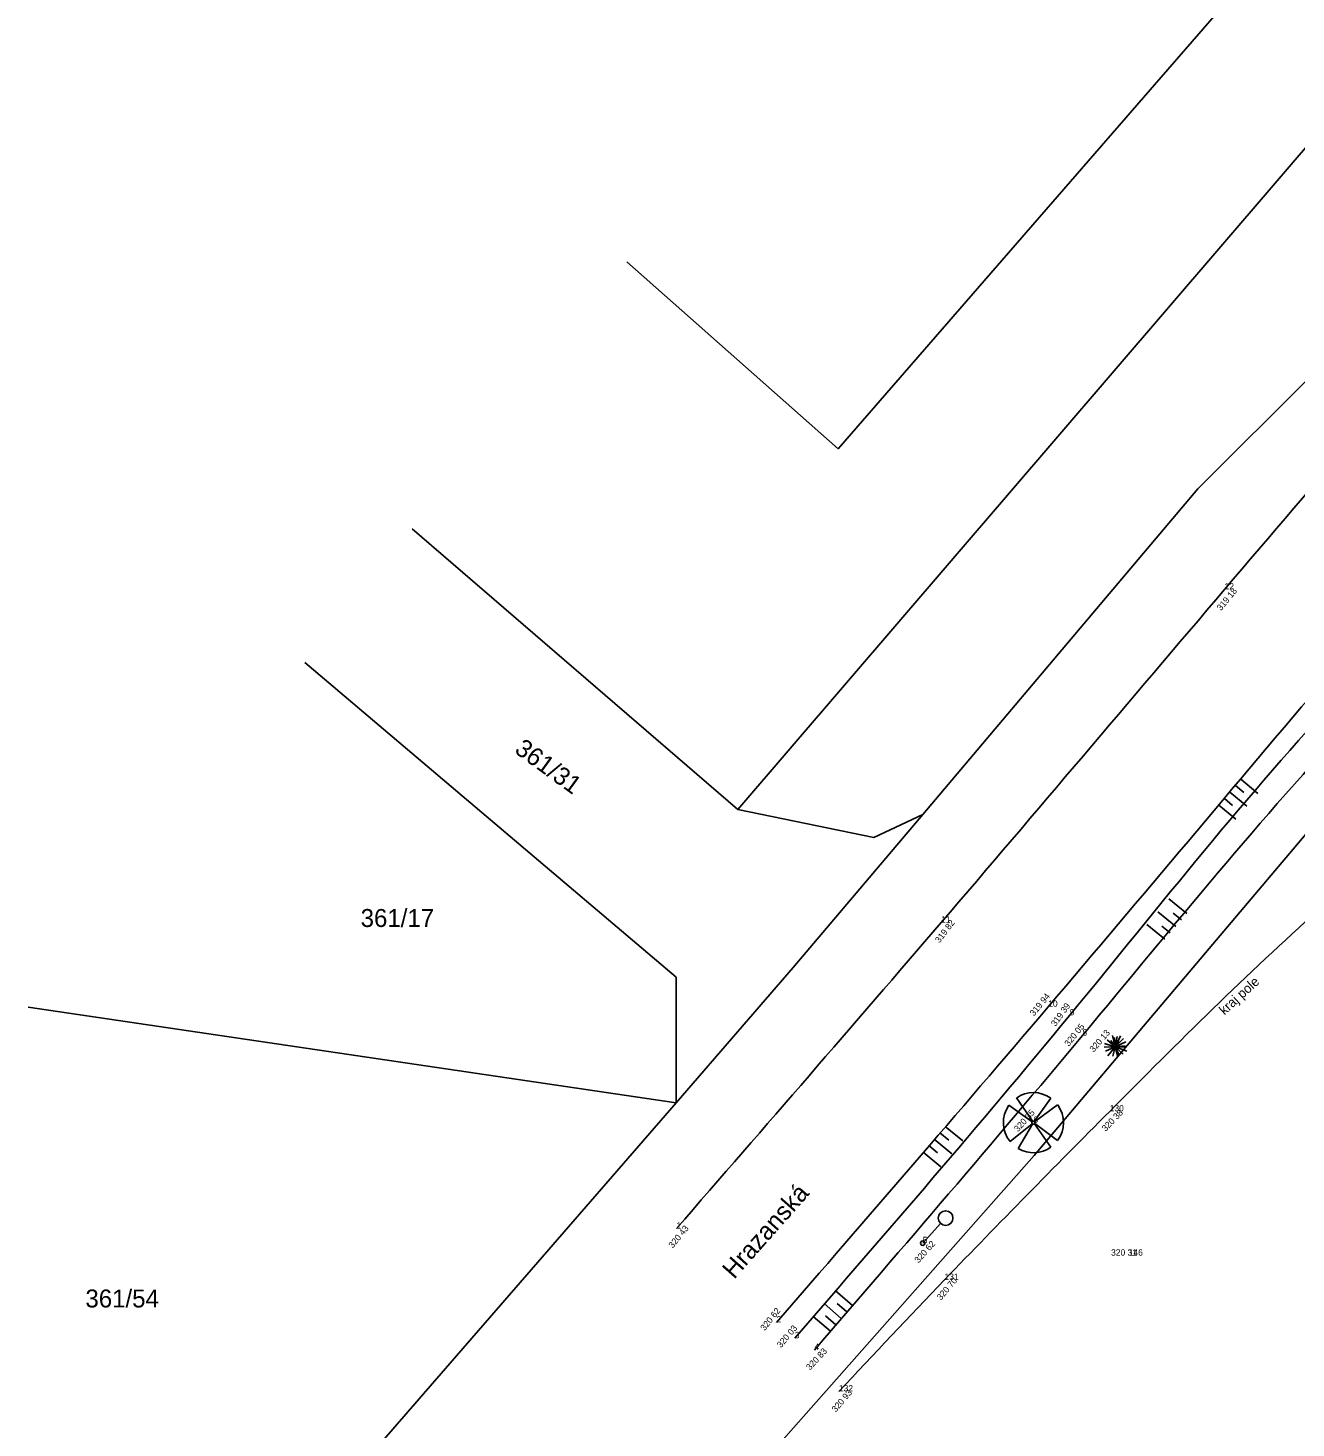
# Model space of a CAD drawing. Extents: x -742884 to -742543, y -1054677 to -1054433.
# Drawn here: x -742813.9 to -742753.9, y -1054546.4 to -1054480.1 of the extents above; entities that cross this region are included whole.
import ezdxf

# ---------------------------------------------------------------- set-up
doc = ezdxf.new("R2010")
doc.units = 0
for name, color, linetype in [('Vrstva 1', 7, 'Continuous'), ('Vrstva 10', 7, 'Continuous'), ('Vrstva 11', 7, 'Continuous'), ('Vrstva 14', 7, 'Continuous'), ('Vrstva 15', 7, 'Continuous'), ('Vrstva 2', 7, 'Continuous'), ('Vrstva 3', 7, 'Continuous'), ('Vrstva 4', 7, 'Continuous'), ('Vrstva 50', 7, 'Continuous')]:
    doc.layers.add(name, color=color, linetype=linetype)

# ---------------------------------------------------------------- blocks, each defined once
blk = doc.blocks.new('Z15')
at = {"layer": 'Vrstva 2'}
for p, q in [((-10, 2), (-8, 6)), ((-10, -2), (-10, 2)), ((-8, 6), (-6, 8)), ((-6, 8), (-2, 10)), ((-2, 10), (2, 10)), ((2, 10), (6, 8)), ((6, 8), (8, 6)), ((8, 6), (10, 2)), ((10, 2), (10, -2)), ((-8, -6), (-10, -2)), ((-6, -8), (-8, -6)), ((-2, -10), (-6, -8)), ((2, -10), (-2, -10)), ((6, -8), (2, -10)), ((8, -6), (6, -8)), ((10, -2), (8, -6))]:
    blk.add_line(p, q, dxfattribs=at)

msp = doc.modelspace()

# ---------------------------------------------------------------- linework, layer by layer
at = {"layer": 'Vrstva 1'}
for p, q in [((-742757.28, -1054506.67), (-742757.28, -1054506.67)), ((-742770.7, -1054522.44), (-742770.7, -1054522.44)), ((-742765.63, -1054526.43), (-742765.63, -1054526.43)), ((-742764.61, -1054526.83), (-742764.61, -1054526.83)), ((-742764.01, -1054527.79), (-742764.01, -1054527.79)), ((-742762.46, -1054528.33), (-742762.46, -1054528.33)), ((-742766.33, -1054531.92), (-742766.33, -1054531.92)), ((-742762.72, -1054531.38), (-742762.72, -1054531.38)), ((-742783.23, -1054536.93), (-742783.23, -1054536.93)), ((-742771.57, -1054537.62), (-742771.57, -1054537.62)), ((-742761.82, -1054538.21), (-742761.82, -1054538.21)), ((-742770.54, -1054539.36), (-742770.54, -1054539.36)), ((-742778.49, -1054541.37), (-742778.49, -1054541.37)), ((-742777.63, -1054542.12), (-742777.63, -1054542.12)), ((-742776.7, -1054542.68), (-742776.7, -1054542.68)), ((-742775.54, -1054544.64), (-742775.54, -1054544.64))]:
    msp.add_line(p, q, dxfattribs=at)
at = {"layer": 'Vrstva 10'}
for p, q in [((-742762.46, -1054528.33), (-742762.835, -1054528.001)), ((-742762.46, -1054528.33), (-742762.671, -1054528.018)), ((-742762.46, -1054528.33), (-742762.593, -1054527.791)), ((-742762.46, -1054528.33), (-742762.494, -1054527.876)), ((-742762.46, -1054528.33), (-742762.212, -1054527.805)), ((-742762.46, -1054528.33), (-742762.367, -1054527.839)), ((-742762.46, -1054528.33), (-742762.064, -1054527.925)), ((-742762.46, -1054528.33), (-742762.986, -1054528.344)), ((-742762.46, -1054528.33), (-742762.959, -1054528.173)), ((-742762.46, -1054528.33), (-742762.915, -1054528.532)), ((-742762.46, -1054528.33), (-742762.805, -1054528.748)), ((-742762.46, -1054528.33), (-742762.575, -1054528.771)), ((-742762.464, -1054528.328), (-742762.464, -1054528.328)), ((-742762.46, -1054528.33), (-742761.952, -1054528.085)), ((-742762.46, -1054528.33), (-742761.983, -1054528.277)), ((-742762.46, -1054528.33), (-742762.46, -1054528.33)), ((-742762.46, -1054528.33), (-742762.289, -1054528.671)), ((-742762.46, -1054528.33), (-742761.91, -1054528.53)), ((-742762.46, -1054528.33), (-742761.983, -1054528.346)), ((-742762.46, -1054528.33), (-742762.079, -1054528.665)), ((-742762.46, -1054528.33), (-742762.338, -1054528.804)), ((-742762.46, -1054528.33), (-742762.46, -1054528.33)), ((-742766.384, -1054531.871), (-742767.49, -1054531.093)), ((-742766.363, -1054531.863), (-742767.138, -1054530.747)), ((-742766.289, -1054531.863), (-742765.504, -1054530.757)), ((-742766.277, -1054531.879), (-742765.185, -1054531.071)), ((-742766.387, -1054531.968), (-742767.435, -1054532.81)), ((-742766.373, -1054531.982), (-742767.046, -1054533.146)), ((-742766.282, -1054531.977), (-742765.502, -1054533.076)), ((-742766.27, -1054531.961), (-742765.185, -1054532.762))]:
    msp.add_line(p, q, dxfattribs=at)
for centre, radius, start, end in [((-742766.327, -1054531.915), 1.422, 54.74653, 124.81053), ((-742766.328, -1054531.912), 1.423, 144.87673, 218.93364), ((-742766.327, -1054531.915), 1.422, 323.47555, 36.29708), ((-742766.327, -1054531.915), 1.422, 239.61513, 305.45522)]:
    msp.add_arc(centre, radius, start, end, dxfattribs=at)
at = {"layer": 'Vrstva 11'}
for p, q in [((-742756.369, -1054516.288), (-742756.768, -1054515.956)), ((-742755.712, -1054516.324), (-742756.513, -1054515.653)), ((-742757.287, -1054516.574), (-742756.909, -1054516.891)), ((-742757.028, -1054516.265), (-742756.227, -1054516.934)), ((-742757.547, -1054516.882), (-742756.748, -1054517.552)), ((-742759.064, -1054522.013), (-742759.925, -1054521.311)), ((-742759.589, -1054522.625), (-742760.448, -1054521.928)), ((-742759.327, -1054522.319), (-742759.721, -1054521.998)), ((-742760.963, -1054522.537), (-742760.11, -1054523.232)), ((-742760.252, -1054522.609), (-742759.853, -1054522.932)), ((-742770.329, -1054532.748), (-742770.76, -1054532.389)), ((-742769.677, -1054532.78), (-742770.501, -1054532.089)), ((-742771.55, -1054533.307), (-742770.719, -1054534.004)), ((-742771.286, -1054533.001), (-742770.869, -1054533.351)), ((-742771.024, -1054532.696), (-742770.194, -1054533.388)), ((-742774.902, -1054540.571), (-742775.71, -1054539.865)), ((-742775.425, -1054541.184), (-742776.234, -1054540.481)), ((-742775.164, -1054540.878), (-742775.627, -1054540.474)), ((-742776.751, -1054541.088), (-742775.944, -1054541.792)), ((-742776.178, -1054541.066), (-742775.688, -1054541.492))]:
    msp.add_line(p, q, dxfattribs=at)
for points in [[(-742777.63, -1054542.12), (-742764.61, -1054526.83), (-742751.7, -1054511.56), (-742738.47, -1054495.82), (-742727.02, -1054482.18), (-742726.38, -1054482.19), (-742725.15, -1054482.94)], [(-742776.7, -1054542.68), (-742764.01, -1054527.79), (-742751.11, -1054512.75), (-742737.61, -1054496.47), (-742726.42, -1054483.98), (-742725.9, -1054484.03), (-742714, -1054491.86), (-742704.819, -1054497.481), (-742700.94, -1054500.269), (-742696.44, -1054503.39), (-742688.83, -1054509.5), (-742682.54, -1054514.17), (-742675.15, -1054519.77), (-742673.01, -1054522.11), (-742671.05, -1054524.7)], [(-742641.45, -1054542), (-742646.08, -1054542.32), (-742650.28, -1054545.1), (-742653.63, -1054549.14), (-742658.66, -1054557.13), (-742664.13, -1054565.84), (-742667.81, -1054569.62), (-742669.76, -1054570.07), (-742674.4, -1054567.88), (-742684.66, -1054562.03), (-742693.02, -1054556.88), (-742694.43, -1054554.37), (-742693.99, -1054552.67), (-742684.52, -1054539.64), (-742677.51, -1054529.95), (-742676.26, -1054526.54), (-742677.27, -1054522.39), (-742681.19, -1054517.29), (-742689.28, -1054510.73), (-742697.86, -1054505.14), (-742704.02, -1054502.75), (-742713.11, -1054501.07), (-742723.98, -1054503.51), (-742736.77, -1054510.1), (-742745.39, -1054515.75), (-742752.81, -1054521.82), (-742762.72, -1054531.38), (-742770.54, -1054539.36), (-742775.54, -1054544.64)]]:
    msp.add_spline(points, degree=3, dxfattribs=at)
at = {"layer": 'Vrstva 14'}
msp.add_line((-742771.57, -1054537.62), (-742770.723, -1054536.69), dxfattribs=at)
for centre, radius in [((-742770.486, -1054536.434), 0.348), ((-742771.57, -1054537.621), 0.105)]:
    msp.add_circle(centre, radius, dxfattribs=at)
at = {"layer": 'Vrstva 4'}
for points in [[(-742783.23, -1054536.93), (-742770.7, -1054522.44), (-742757.28, -1054506.67), (-742744.15, -1054491.3), (-742731.95, -1054477.03), (-742724.73, -1054468.59)], [(-742778.49, -1054541.37), (-742765.63, -1054526.43), (-742752.39, -1054510.77), (-742739.19, -1054495.37), (-742727.3, -1054481.14)]]:
    msp.add_spline(points, degree=3, dxfattribs=at)
at = {"layer": 'Vrstva 50'}
msp.add_line((-742780.33, -1054517.08), (-742715.033, -1054440.982), dxfattribs=at)
for points in [[(-742726.76, -1054443.83), (-742775.58, -1054500.01), (-742785.587, -1054491.163)], [(-742771.57, -1054517.32), (-742758.54, -1054501.91), (-742742.39, -1054485.79), (-742708.76, -1054445.064)], [(-742724.95, -1054484.46), (-742747.39, -1054511.11), (-742766.3, -1054533.47), (-742786.45, -1054556.28), (-742796.57, -1054568.72)], [(-742795.74, -1054503.801), (-742780.33, -1054517.08)], [(-742783.25, -1054530.97), (-742783.25, -1054525.03), (-742800.826, -1054510.131)], [(-742783.25, -1054530.97), (-742777.7, -1054524.57), (-742771.57, -1054517.32)], [(-742771.57, -1054517.32), (-742773.89, -1054518.41), (-742780.33, -1054517.08)], [(-742783.25, -1054530.97), (-742813.929, -1054526.441)], [(-742799.53, -1054550), (-742797.18, -1054547.02), (-742783.25, -1054530.97)]]:
    msp.add_lwpolyline(points, dxfattribs=at)

# ---------------------------------------------------------------- block references
at = {"layer": 'Vrstva 10', "xscale": 0.00710900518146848, "yscale": 0.007109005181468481, "rotation": -30.671756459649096}
msp.add_blockref('Z15', (-742766.33, -1054531.92), dxfattribs=at)

# ---------------------------------------------------------------- texts
at = {"layer": 'Vrstva 15'}
for s, height, rotation, p in [('kraj pole', 0.4539, 42.32724, (-742757.288, -1054526.841)), ('Hrazanská', 0.85, 48.53473, (-742780.501, -1054539.36))]:
    msp.add_text(s, height=height, rotation=rotation, dxfattribs=at).set_placement(p)
at = {"layer": 'Vrstva 2'}
for s, p in [('12', (-742757.28, -1054506.67)), ('11', (-742770.7, -1054522.44)), ('10', (-742765.63, -1054526.43)), ('9', (-742764.61, -1054526.83)), ('8', (-742764.01, -1054527.79)), ('7', (-742762.46, -1054528.33)), ('130', (-742762.72, -1054531.38)), ('6', (-742766.33, -1054531.92)), ('1', (-742783.23, -1054536.93)), ('5', (-742771.57, -1054537.62)), ('146', (-742761.82, -1054538.21)), ('131', (-742770.54, -1054539.36)), ('2', (-742778.49, -1054541.37)), ('3', (-742777.63, -1054542.12)), ('4', (-742776.7, -1054542.68)), ('132', (-742775.54, -1054544.64))]:
    msp.add_text(s, height=0.3, dxfattribs=at).set_placement(p)
at = {"layer": 'Vrstva 3'}
for s, rotation, p in [('319 18 ', 50.43005, (-742757.447, -1054507.698)), ('319 82 ', 52.68398, (-742770.776, -1054523.43)), ('319 94 ', 50.66126, (-742766.3, -1054526.891)), ('319 39 ', 54.2004, (-742765.283, -1054527.383)), ('320 05 ', 51.03768, (-742764.66, -1054528.331)), ('320 13 ', 49.18492, (-742763.481, -1054528.603)), ('320 35 ', 48.19954, (-742767.058, -1054532.374)), ('320 38 ', 46.10703, (-742762.914, -1054532.353)), ('320 43 ', 50.67302, (-742783.405, -1054537.88)), ('320 62 ', 48.38856, (-742771.77, -1054538.587)), ('320 70 ', 49.81153, (-742770.706, -1054540.344)), ('320 62 ', 51.55148, (-742779.051, -1054541.793)), ('320 03 ', 49.844, (-742778.278, -1054542.597)), ('320 83 ', 47.2348, (-742776.906, -1054543.657)), ('320 93 ', 49.64408, (-742775.687, -1054545.647))]:
    msp.add_text(s, height=0.3, rotation=rotation, dxfattribs=at).set_placement(p)
msp.add_text('320 31 ', height=0.3, dxfattribs=at).set_placement((-742762.653, -1054538.21))
at = {"layer": 'Vrstva 50'}
msp.add_text('361/31', height=0.85, rotation=324, dxfattribs=at).set_placement((-742790.944, -1054514.364))
for s, p in [('361/17', (-742798.18, -1054522.65)), ('361/54', (-742811.21, -1054540.665))]:
    msp.add_text(s, height=0.85, dxfattribs=at).set_placement(p)

doc.saveas('drawing.dxf')
